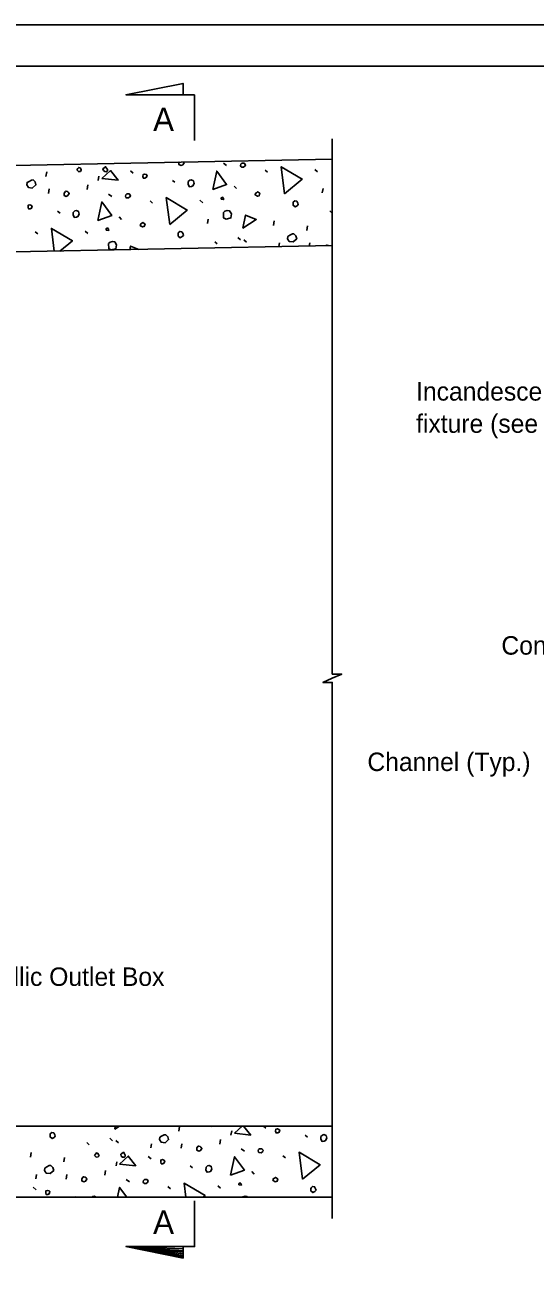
# Model space of a CAD drawing. Extents: x 0 to 30.8, y 0 to 21.2.
# Drawn here: x 8.29 to 12.47, y 9.63 to 19.8 of the extents above; entities that cross this region are included whole.
import ezdxf

# ---------------------------------------------------------------- set-up
doc = ezdxf.new("R2010")
doc.units = 0
for name, color, linetype in [('ActivePts-ConstElements', 7, 'Continuous'), ('Dimension', 7, 'Continuous'), ('Miscellaneous', 7, 'Continuous'), ('Miscellaneous1', 7, 'Continuous'), ('SupstrConc', 7, 'Continuous'), ('TextStructures', 7, 'Continuous')]:
    doc.layers.add(name, color=color, linetype=linetype)

msp = doc.modelspace()

# ---------------------------------------------------------------- linework, layer by layer
at = {"layer": 'ActivePts-ConstElements'}
msp.add_lwpolyline([(0, 0), (30.788, 0), (30.788, 19.46), (0, 19.46)], close=True, dxfattribs=at)
at = {"layer": 'Dimension'}
for p, q in [((9.114, 19.227), (9.583, 19.32)), ((9.583, 19.32), (9.583, 19.227)), ((9.677, 19.227), (9.114, 19.227)), ((9.677, 18.852), (9.677, 19.227)), ((9.677, 10.161), (9.677, 9.786)), ((9.583, 9.768), (9.114, 9.786)), ((9.114, 9.786), (9.583, 9.753)), ((9.583, 9.74), (9.114, 9.786)), ((9.114, 9.786), (9.583, 9.726)), ((9.583, 9.713), (9.114, 9.786)), ((9.114, 9.786), (9.583, 9.703)), ((9.677, 9.786), (9.114, 9.786)), ((9.114, 9.786), (9.583, 9.692)), ((9.583, 9.692), (9.583, 9.786))]:
    msp.add_line(p, q, dxfattribs=at)
for points in [[(9.583, 19.227), (9.583, 19.32), (9.114, 19.227)], [(9.583, 9.786), (9.583, 9.692), (9.114, 9.786)]]:
    msp.add_lwpolyline(points, close=True, dxfattribs=at)
for points in [[(10.805, 10.016), (10.805, 14.411), (10.728, 14.411), (10.805, 14.445), (10.883, 14.479), (10.805, 14.479), (10.805, 18.866)], [(9.677, 10.161), (9.677, 9.786), (9.114, 9.786), (9.583, 9.692), (9.583, 9.786)]]:
    msp.add_lwpolyline(points, dxfattribs=at)
at = {"layer": 'Miscellaneous'}
for p, q in [((9.42, 18.67), (9.421, 18.671)), ((9.914, 18.665), (9.939, 18.646)), ((10.255, 18.608), (10.275, 18.591)), ((10.662, 18.614), (10.685, 18.595)), ((8.459, 18.557), (8.465, 18.595)), ((8.887, 18.524), (8.893, 18.56)), ((9.151, 18.603), (9.174, 18.583)), ((9.496, 18.524), (9.515, 18.509)), ((8.479, 18.417), (8.484, 18.455)), ((8.796, 18.451), (8.801, 18.488)), ((8.972, 18.412), (8.998, 18.393)), ((10, 18.478), (10.021, 18.458)), ((10.723, 18.424), (10.73, 18.459)), ((9.313, 18.356), (9.333, 18.338)), ((9.72, 18.362), (9.744, 18.342)), ((8.554, 18.272), (8.574, 18.256)), ((9.058, 18.226), (9.079, 18.205)), ((9.782, 18.171), (9.788, 18.206)), ((10.784, 18.274), (10.805, 18.256)), ((8.371, 18.104), (8.391, 18.086)), ((8.779, 18.109), (8.802, 18.09)), ((10.324, 18.156), (10.33, 18.194)), ((10.596, 18.115), (10.602, 18.153)), ((9.842, 18.022), (9.863, 18.004)), ((10.032, 18.057), (10.053, 18.037)), ((10.081, 18.039), (10.102, 18.019)), ((10.367, 17.982), (10.373, 18.014)), ((10.617, 17.987), (10.621, 18.013)), ((8.846, 17.951), (8.846, 17.954)), ((9.274, 10.773), (9.274, 10.774)), ((9.547, 10.732), (9.552, 10.77)), ((9.975, 10.699), (9.981, 10.734)), ((10.242, 10.774), (10.262, 10.758)), ((10.583, 10.699), (10.603, 10.684)), ((8.793, 10.639), (8.813, 10.621)), ((8.982, 10.674), (9.003, 10.654)), ((9.031, 10.656), (9.052, 10.636)), ((9.317, 10.595), (9.323, 10.63)), ((9.566, 10.592), (9.571, 10.63)), ((9.883, 10.625), (9.889, 10.663)), ((10.059, 10.587), (10.085, 10.568)), ((8.333, 10.52), (8.338, 10.558)), ((8.605, 10.48), (8.61, 10.517)), ((9.033, 10.447), (9.039, 10.482)), ((9.297, 10.525), (9.32, 10.505)), ((10.4, 10.531), (10.421, 10.513)), ((8.375, 10.343), (8.381, 10.378)), ((8.624, 10.34), (8.63, 10.377)), ((8.941, 10.373), (8.947, 10.411)), ((9.641, 10.447), (9.661, 10.431)), ((10.145, 10.401), (10.166, 10.38)), ((8.355, 10.273), (8.378, 10.253)), ((9.117, 10.335), (9.143, 10.316)), ((9.458, 10.279), (9.479, 10.261)), ((9.866, 10.284), (9.889, 10.265)), ((8.699, 10.194), (8.704, 10.191))]:
    msp.add_line(p, q, dxfattribs=at)
for points in [[(8.711, 18.612), (8.725, 18.597), (8.741, 18.599), (8.748, 18.609), (8.747, 18.613), (8.738, 18.627), (8.727, 18.631), (8.719, 18.621), (8.711, 18.612)], [(8.917, 18.54), (8.987, 18.605), (9.05, 18.526), (8.917, 18.54)], [(8.93, 18.606), (8.94, 18.598), (8.953, 18.596), (8.962, 18.604), (8.962, 18.614), (8.956, 18.625), (8.948, 18.636), (8.935, 18.628), (8.926, 18.62), (8.93, 18.606)], [(9.549, 18.673), (9.549, 18.655), (9.566, 18.647), (9.58, 18.653), (9.591, 18.669), (9.587, 18.675)], [(9.55, 18.674), (9.549, 18.673)], [(10.055, 18.638), (10.061, 18.634), (10.077, 18.633), (10.09, 18.645), (10.093, 18.653), (10.084, 18.666), (10.063, 18.666), (10.055, 18.658), (10.053, 18.648), (10.055, 18.638)], [(10.415, 18.416), (10.387, 18.636), (10.559, 18.535), (10.415, 18.416)], [(8.302, 18.489), (8.315, 18.467), (8.347, 18.462), (8.377, 18.488), (8.37, 18.513), (8.353, 18.529), (8.34, 18.528), (8.32, 18.517), (8.304, 18.508), (8.302, 18.489)], [(9.254, 18.558), (9.258, 18.543), (9.27, 18.544), (9.282, 18.55), (9.287, 18.567), (9.281, 18.573), (9.269, 18.577), (9.255, 18.573), (9.254, 18.558)], [(9.625, 18.515), (9.624, 18.491), (9.634, 18.473), (9.651, 18.475), (9.663, 18.481), (9.673, 18.499), (9.667, 18.521), (9.65, 18.529), (9.637, 18.526), (9.625, 18.515)], [(9.826, 18.45), (9.858, 18.601), (9.939, 18.49), (9.826, 18.45)], [(8.607, 18.421), (8.607, 18.402), (8.625, 18.394), (8.638, 18.401), (8.65, 18.417), (8.642, 18.427), (8.635, 18.433), (8.624, 18.436), (8.619, 18.434), (8.607, 18.421)], [(9.113, 18.386), (9.12, 18.382), (9.135, 18.381), (9.148, 18.392), (9.151, 18.401), (9.142, 18.414), (9.121, 18.414), (9.113, 18.406), (9.111, 18.395), (9.113, 18.386)], [(10.174, 18.406), (10.193, 18.395), (10.207, 18.399), (10.212, 18.419), (10.193, 18.432), (10.185, 18.424), (10.176, 18.419), (10.174, 18.406), (10.173, 18.411)], [(8.312, 18.305), (8.316, 18.291), (8.329, 18.292), (8.34, 18.297), (8.346, 18.314), (8.339, 18.32), (8.327, 18.325), (8.313, 18.321), (8.312, 18.305)], [(8.884, 18.197), (8.916, 18.348), (8.998, 18.238), (8.884, 18.197)], [(9.473, 18.164), (9.445, 18.384), (9.617, 18.282), (9.473, 18.164)], [(9.894, 18.37), (9.915, 18.367), (9.913, 18.377), (9.905, 18.388), (9.894, 18.38), (9.894, 18.37)], [(10.485, 18.339), (10.484, 18.321), (10.501, 18.307), (10.517, 18.316), (10.527, 18.327), (10.524, 18.339), (10.514, 18.355), (10.498, 18.358), (10.485, 18.347), (10.485, 18.339)], [(8.683, 18.262), (8.682, 18.239), (8.692, 18.221), (8.709, 18.223), (8.721, 18.229), (8.731, 18.247), (8.726, 18.269), (8.708, 18.277), (8.696, 18.274), (8.683, 18.262)], [(9.913, 18.261), (9.914, 18.217), (9.935, 18.207), (9.947, 18.21), (9.974, 18.217), (9.978, 18.25), (9.964, 18.274), (9.945, 18.277), (9.926, 18.272), (9.913, 18.261)], [(10.072, 18.132), (10.095, 18.24), (10.182, 18.203), (10.072, 18.132)], [(8.527, 17.945), (8.503, 18.131), (8.676, 18.03), (8.573, 17.946)], [(8.952, 18.117), (8.974, 18.115), (8.971, 18.125), (8.963, 18.136), (8.952, 18.128), (8.952, 18.117)], [(9.233, 18.153), (9.251, 18.143), (9.265, 18.147), (9.271, 18.166), (9.252, 18.179), (9.243, 18.172), (9.234, 18.167), (9.233, 18.153), (9.231, 18.158)], [(9.543, 18.087), (9.543, 18.068), (9.559, 18.055), (9.575, 18.064), (9.585, 18.074), (9.582, 18.087), (9.572, 18.102), (9.556, 18.106), (9.543, 18.094), (9.543, 18.087)], [(8.971, 18.008), (8.973, 17.965), (8.993, 17.955), (9.005, 17.958), (9.032, 17.965), (9.036, 17.997), (9.022, 18.022), (9.003, 18.025), (8.984, 18.019), (8.971, 18.008)], [(10.439, 18.047), (10.452, 18.025), (10.485, 18.02), (10.514, 18.046), (10.507, 18.071), (10.49, 18.087), (10.478, 18.086), (10.457, 18.075), (10.441, 18.066), (10.439, 18.047)], [(9.147, 17.957), (9.153, 17.987), (9.221, 17.959)], [(10.774, 17.99), (10.772, 17.991), (10.761, 17.994), (10.756, 17.992), (10.754, 17.99)], [(8.493, 10.703), (8.493, 10.685), (8.509, 10.671), (8.525, 10.681), (8.535, 10.691), (8.532, 10.703), (8.523, 10.719), (8.506, 10.722), (8.494, 10.711), (8.493, 10.703)], [(9.022, 10.749), (9.027, 10.774)], [(9.061, 10.774), (9.022, 10.749)], [(9.389, 10.664), (9.403, 10.642), (9.435, 10.637), (9.464, 10.663), (9.458, 10.687), (9.44, 10.703), (9.428, 10.703), (9.407, 10.692), (9.392, 10.683), (9.389, 10.664)], [(9.811, 10.774), (9.813, 10.772), (9.828, 10.774), (9.828, 10.774)], [(10.004, 10.715), (10.068, 10.774)], [(10.079, 10.774), (10.137, 10.701), (10.004, 10.715)], [(10.026, 10.774), (10.027, 10.773), (10.041, 10.771), (10.044, 10.774)], [(10.341, 10.732), (10.345, 10.718), (10.358, 10.719), (10.369, 10.724), (10.375, 10.742), (10.368, 10.747), (10.356, 10.752), (10.342, 10.748), (10.341, 10.732)], [(10.712, 10.69), (10.711, 10.666), (10.721, 10.648), (10.738, 10.65), (10.75, 10.656), (10.76, 10.674), (10.755, 10.696), (10.737, 10.704), (10.725, 10.701), (10.712, 10.69)], [(9.694, 10.595), (9.694, 10.577), (9.712, 10.569), (9.726, 10.575), (9.737, 10.591), (9.729, 10.602), (9.722, 10.608), (9.711, 10.61), (9.706, 10.609), (9.694, 10.595)], [(10.201, 10.56), (10.207, 10.557), (10.223, 10.556), (10.235, 10.567), (10.238, 10.576), (10.229, 10.589), (10.209, 10.588), (10.2, 10.581), (10.198, 10.57), (10.201, 10.56)], [(8.857, 10.534), (8.871, 10.52), (8.886, 10.521), (8.894, 10.531), (8.893, 10.536), (8.884, 10.549), (8.872, 10.554), (8.865, 10.544), (8.857, 10.534)], [(9.062, 10.462), (9.133, 10.528), (9.195, 10.449), (9.062, 10.462)], [(9.076, 10.528), (9.086, 10.52), (9.099, 10.519), (9.107, 10.526), (9.107, 10.536), (9.102, 10.548), (9.094, 10.559), (9.08, 10.55), (9.072, 10.543), (9.076, 10.528)], [(9.399, 10.48), (9.403, 10.466), (9.416, 10.466), (9.427, 10.472), (9.433, 10.489), (9.426, 10.495), (9.415, 10.5), (9.4, 10.496), (9.399, 10.48)], [(9.972, 10.372), (10.004, 10.523), (10.085, 10.413), (9.972, 10.372)], [(10.561, 10.338), (10.533, 10.559), (10.705, 10.457), (10.561, 10.338)], [(8.447, 10.411), (8.461, 10.389), (8.493, 10.385), (8.522, 10.411), (8.516, 10.435), (8.499, 10.451), (8.486, 10.45), (8.465, 10.44), (8.45, 10.43), (8.447, 10.411)], [(9.771, 10.437), (9.769, 10.414), (9.779, 10.396), (9.797, 10.398), (9.808, 10.403), (9.819, 10.422), (9.813, 10.443), (9.795, 10.452), (9.783, 10.448), (9.771, 10.437)], [(8.753, 10.343), (8.752, 10.325), (8.77, 10.317), (8.784, 10.323), (8.795, 10.339), (8.787, 10.35), (8.78, 10.356), (8.769, 10.358), (8.765, 10.357), (8.753, 10.343)], [(9.045, 10.191), (9.062, 10.271), (9.121, 10.191)], [(9.259, 10.308), (9.265, 10.304), (9.281, 10.303), (9.294, 10.315), (9.296, 10.323), (9.288, 10.336), (9.267, 10.336), (9.259, 10.329), (9.256, 10.318), (9.259, 10.308)], [(9.605, 10.191), (9.591, 10.306), (9.763, 10.205), (9.746, 10.191)], [(10.04, 10.292), (10.061, 10.29), (10.058, 10.3), (10.05, 10.31), (10.04, 10.302), (10.04, 10.292)], [(10.32, 10.328), (10.338, 10.318), (10.353, 10.322), (10.358, 10.341), (10.339, 10.354), (10.331, 10.347), (10.322, 10.342), (10.32, 10.328), (10.319, 10.333)], [(10.63, 10.261), (10.63, 10.243), (10.647, 10.229), (10.662, 10.239), (10.672, 10.249), (10.669, 10.261), (10.66, 10.277), (10.643, 10.28), (10.631, 10.269), (10.63, 10.261)], [(8.458, 10.228), (8.461, 10.213), (8.474, 10.214), (8.486, 10.22), (8.491, 10.237), (8.485, 10.243), (8.473, 10.247), (8.458, 10.244), (8.458, 10.228)], [(8.871, 10.191), (8.871, 10.191), (8.853, 10.199), (8.841, 10.196), (8.835, 10.191)], [(10.113, 10.191), (10.109, 10.197), (10.09, 10.199), (10.071, 10.194), (10.067, 10.191)]]:
    msp.add_lwpolyline(points, dxfattribs=at)
at = {"layer": 'Miscellaneous1'}
msp.add_lwpolyline([(0, 19.8), (30.8, 19.8), (30.8, 0), (0, 0)], close=True, dxfattribs=at)
at = {"layer": 'SupstrConc'}
for p, q in [((0.617, 18.495), (10.805, 18.699)), ((7.811, 17.931), (10.805, 17.991)), ((10.805, 10.774), (7.061, 10.774)), ((10.805, 10.191), (6.519, 10.191))]:
    msp.add_line(p, q, dxfattribs=at)

# ---------------------------------------------------------------- texts
at = {"layer": 'Dimension'}
for s, p in [('Incandescent Light', (11.492, 16.72)), ('fixture (see Note 15)', (11.492, 16.456)), ('Channel (Typ.)', (11.093, 13.684))]:
    msp.add_text(s, height=0.1512, dxfattribs=at).set_placement(p)
at = {"layer": 'TextStructures'}
for s, height, p in [('A', 0.192, (9.337, 18.929)), ('Conduit (120V)', 0.1512, (12.191, 14.638)), ('Nonmetallic Outlet Box', 0.1512, (7.373, 11.923)), ('A', 0.192, (9.337, 9.891))]:
    msp.add_text(s, height=height, dxfattribs=at).set_placement(p)

doc.saveas('drawing.dxf')
